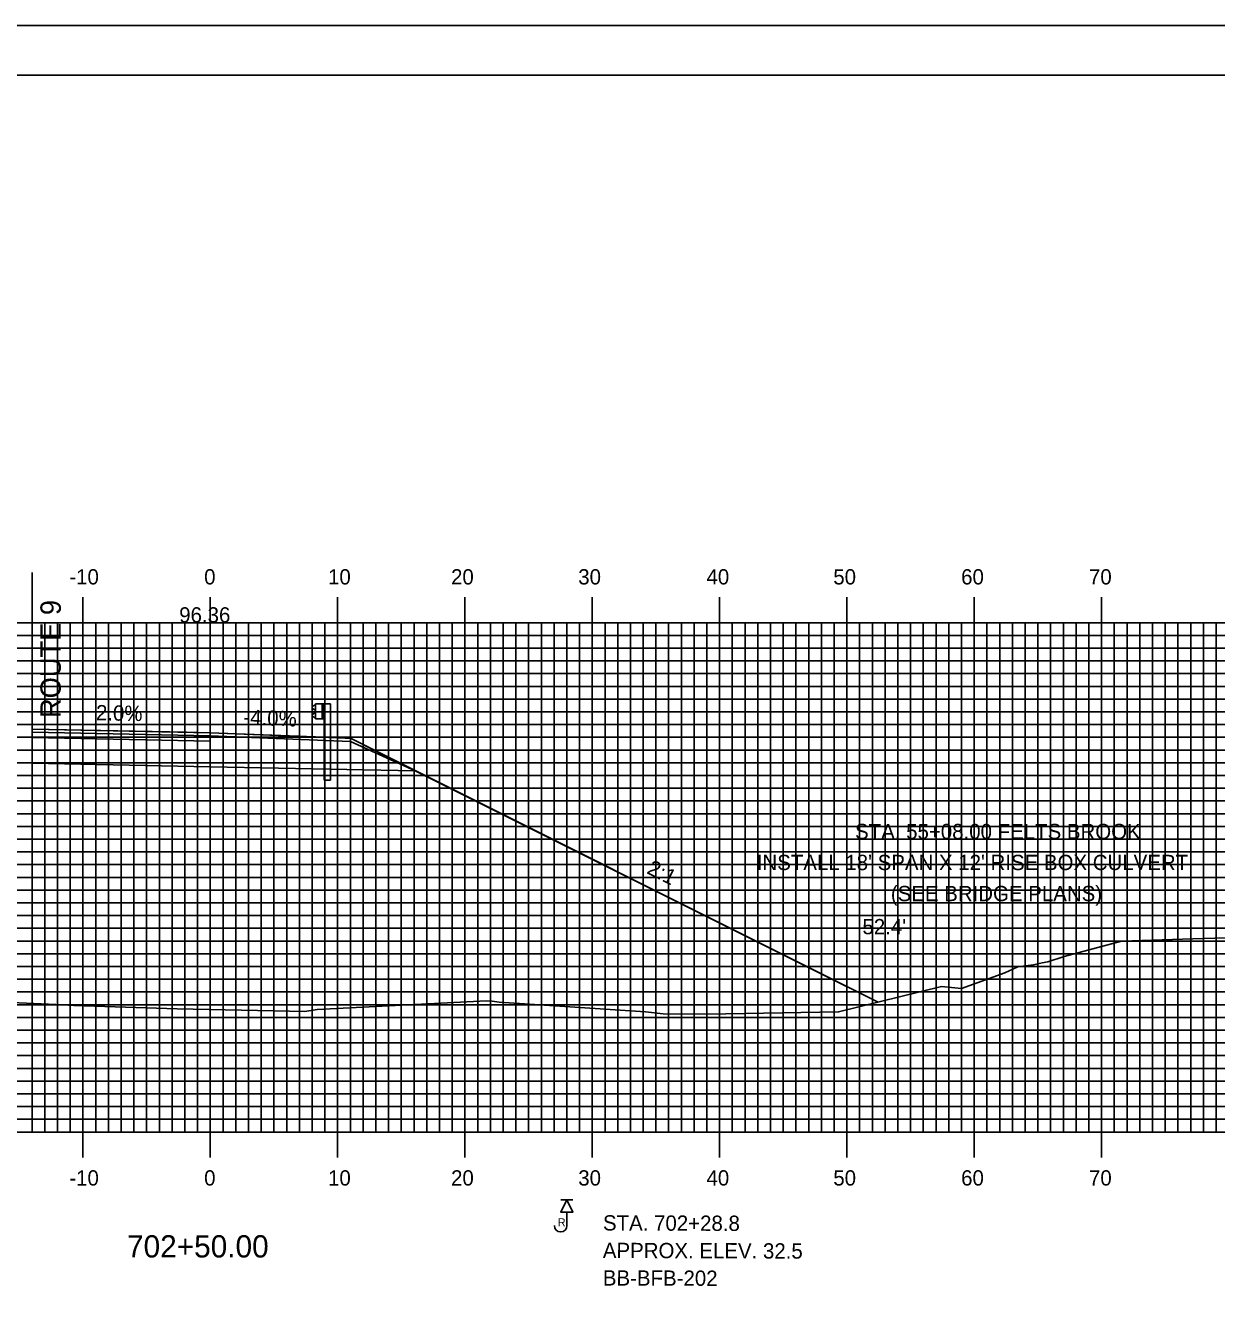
# Model space of a CAD drawing. Extents: x 852936 to 853279, y 364366 to 364586.
# Drawn here: x 853087.2 to 853180.7, y 364484.9 to 364585.7 of the extents above; entities that cross this region are included whole.
import ezdxf

# ---------------------------------------------------------------- set-up
doc = ezdxf.new("R2010")
doc.units = 0
for name, color, linetype in [('ANNOTATION', 7, 'Continuous'), ('BORDER', 7, 'Continuous'), ('BORING - REFUSAL', 7, 'Continuous'), ('D_Guardrail_Beam_Rt', 7, 'Continuous'), ('D_Roadway_Centerline', 7, 'Continuous'), ('D_Roadway_Centerline_Text', 7, 'Continuous'), ('D_Roadway_Edge_Shoulder', 7, 'Continuous'), ('D_Roadway_Edge_TW', 7, 'Continuous'), ('D_Roadway_Pavement', 7, 'Continuous'), ('D_Roadway_SlopeLines', 7, 'Continuous'), ('D_Roadway_SubGrade', 7, 'Continuous'), ('D_Text_Standard', 7, 'Continuous'), ('H_V ANNOTATION', 7, 'Continuous'), ('MAJOR', 7, 'Continuous'), ('MINOR', 7, 'Continuous'), ('PLOT BOUNDARY', 7, 'Continuous'), ('S_Roadway_Centerline', 7, 'Continuous')]:
    doc.layers.add(name, color=color, linetype=linetype)

msp = doc.modelspace()

# ---------------------------------------------------------------- linework, layer by layer
at = {"layer": 'BORDER'}
msp.add_lwpolyline([(852952.09, 364371.79), (853272.09, 364371.79), (853272.09, 364581.79), (852952.09, 364581.79)], close=True, dxfattribs=at)
at = {"layer": 'BORING - REFUSAL'}
for p, q in [((853130.17, 364493.46), (853129.21, 364493.46)), ((853129.69, 364492.5), (853129.69, 364491.44))]:
    msp.add_line(p, q, dxfattribs=at)
msp.add_lwpolyline([(853129.69, 364493.46), (853130.17, 364492.5), (853129.21, 364492.5)], close=True, dxfattribs=at)
msp.add_arc((853129.21, 364491.44), 0.485, 180, 0, dxfattribs=at)
at = {"layer": 'D_Guardrail_Beam_Rt'}
for p, q in [((853109.87, 364532.3), (853109.73, 364532.2)), ((853109.73, 364532.06), (853109.92, 364531.93)), ((853109.96, 364532.33), (853109.89, 364532.31)), ((853109.96, 364532.41), (853110.65, 364532.41)), ((853109.96, 364531.24), (853109.96, 364532.41)), ((853109.96, 364531.86), (853109.96, 364531.79)), ((853110.48, 364532.41), (853110.48, 364531.24)), ((853110.59, 364532.41), (853110.59, 364531.24)), ((853110.65, 364532.41), (853111.12, 364532.41)), ((853110.65, 364532.41), (853110.65, 364531.24)), ((853111.12, 364532.41), (853111.12, 364526.41)), ((853109.92, 364531.73), (853109.73, 364531.59)), ((853109.73, 364531.45), (853109.87, 364531.35)), ((853109.89, 364531.34), (853109.96, 364531.33)), ((853110.65, 364531.24), (853109.96, 364531.24)), ((853110.63, 364526.41), (853110.63, 364531.24)), ((853110.63, 364526.41), (853111.12, 364526.41))]:
    msp.add_line(p, q, dxfattribs=at)
for centre, major_axis, start_param, end_param in [((853109.78, 364532.13), (-0.0877, 0), 5.323254, 7.243116), ((853109.9, 364532.27), (-0.0417, 0), 4.907132, 5.323254), ((853109.88, 364531.86), (0.0789, 0), 0, 0.959931), ((853109.78, 364531.52), (-0.0877, 0), 5.323254, 7.243116), ((853109.9, 364531.38), (-0.0417, 0), 0.959931, 1.376053), ((853109.88, 364531.79), (0.0789, 0), 5.323254, 6.283185)]:
    msp.add_ellipse(centre, major_axis=major_axis, ratio=0.995501, start_param=start_param, end_param=end_param, dxfattribs=at)
at = {"layer": 'D_Roadway_Centerline'}
msp.add_lwpolyline([(853087.69, 364530.43), (853099.81, 364530.18), (853101.69, 364530.15), (853108.62, 364529.87), (853109.69, 364529.83), (853112.29, 364529.72), (853112.69, 364529.71), (853117.1, 364527.5), (853117.79, 364527.16), (853149.2, 364511.45), (853154.14, 364508.98)], dxfattribs=at)
at = {"layer": 'D_Roadway_Edge_Shoulder'}
for points in [[(853101.69, 364530.15), (853112.69, 364529.71), (853112.69, 364529.46), (853101.69, 364529.9)], [(853101.69, 364530.15), (853109.69, 364529.83), (853109.69, 364529.83), (853112.69, 364529.71), (853112.69, 364529.46), (853101.69, 364529.9)], [(853101.69, 364530.15), (853109.69, 364529.83), (853109.69, 364529.83), (853112.69, 364529.71), (853112.69, 364529.46), (853101.69, 364529.9)], [(853101.69, 364530.15), (853112.69, 364529.71), (853112.69, 364529.46), (853101.69, 364529.9)], [(853101.69, 364530.15), (853112.69, 364529.71), (853112.69, 364529.46), (853101.69, 364529.9)]]:
    msp.add_lwpolyline(points, close=True, dxfattribs=at)
at = {"layer": 'D_Roadway_Edge_TW'}
msp.add_lwpolyline([(853087.69, 364530.43), (853101.69, 364530.15), (853101.69, 364529.9), (853087.69, 364530.18)], close=True, dxfattribs=at)
msp.add_lwpolyline([(853087.69, 364530.43), (853101.69, 364530.15), (853101.69, 364529.9), (853087.69, 364530.18)], close=True, dxfattribs=at)
msp.add_lwpolyline([(853087.69, 364530.43), (853101.69, 364530.15), (853101.69, 364529.9), (853087.69, 364530.18)], close=True, dxfattribs=at)
msp.add_lwpolyline([(853087.69, 364530.43), (853101.69, 364530.15), (853101.69, 364529.9), (853087.69, 364530.18)], close=True, dxfattribs=at)
at = {"layer": 'D_Roadway_Pavement'}
msp.add_lwpolyline([(853087.69, 364530.18), (853101.69, 364529.9), (853101.69, 364529.48), (853087.69, 364529.76)], close=True, dxfattribs=at)
msp.add_lwpolyline([(853087.69, 364530.18), (853101.69, 364529.9), (853101.69, 364529.48), (853087.69, 364529.76)], close=True, dxfattribs=at)
msp.add_lwpolyline([(853087.69, 364530.18), (853101.69, 364529.9), (853101.69, 364529.48), (853087.69, 364529.76)], close=True, dxfattribs=at)
msp.add_lwpolyline([(853087.69, 364530.18), (853101.69, 364529.9), (853101.69, 364529.48), (853087.69, 364529.76)], close=True, dxfattribs=at)
msp.add_lwpolyline([(853101.69, 364529.9), (853101.69, 364529.48)], dxfattribs=at)
msp.add_lwpolyline([(853101.69, 364529.9), (853101.69, 364529.48)], dxfattribs=at)
msp.add_lwpolyline([(853101.69, 364529.9), (853101.69, 364529.48)], dxfattribs=at)
msp.add_lwpolyline([(853101.69, 364529.9), (853101.69, 364529.48)], dxfattribs=at)
msp.add_lwpolyline([(853101.69, 364529.9), (853101.69, 364529.48)], dxfattribs=at)
msp.add_lwpolyline([(853101.69, 364529.9), (853101.69, 364529.48)], dxfattribs=at)
msp.add_lwpolyline([(853101.69, 364529.9), (853101.69, 364529.48)], dxfattribs=at)
msp.add_lwpolyline([(853101.69, 364529.9), (853101.69, 364529.48)], dxfattribs=at)
msp.add_lwpolyline([(853101.69, 364529.9), (853101.69, 364529.48)], dxfattribs=at)
msp.add_lwpolyline([(853101.69, 364529.9), (853101.69, 364529.48)], dxfattribs=at)
msp.add_lwpolyline([(853101.69, 364529.9), (853101.69, 364529.48)], dxfattribs=at)
msp.add_lwpolyline([(853101.69, 364529.9), (853101.69, 364529.48)], dxfattribs=at)
msp.add_lwpolyline([(853101.69, 364529.9), (853101.69, 364529.48)], dxfattribs=at)
msp.add_lwpolyline([(853101.69, 364529.9), (853101.69, 364529.48)], dxfattribs=at)
at = {"layer": 'D_Roadway_SlopeLines'}
msp.add_lwpolyline([(853112.69, 364529.71), (853154.14, 364508.98)], dxfattribs=at)
msp.add_lwpolyline([(853112.69, 364529.71), (853154.14, 364508.98)], dxfattribs=at)
msp.add_lwpolyline([(853112.69, 364529.71), (853154.14, 364508.98)], dxfattribs=at)
msp.add_lwpolyline([(853112.69, 364529.71), (853154.14, 364508.98)], dxfattribs=at)
at = {"layer": 'D_Roadway_SubGrade'}
msp.add_line((853087.69, 364542.72), (853087.69, 364527.76), dxfattribs=at)
for points in [[(853101.69, 364529.48), (853101.69, 364529.9), (853112.69, 364529.46), (853112.69, 364529.71), (853117.79, 364527.16), (853101.69, 364527.48)], [(853101.69, 364529.48), (853101.69, 364529.9), (853112.69, 364529.46), (853112.69, 364529.71), (853117.79, 364527.16), (853101.69, 364527.48)], [(853101.69, 364529.48), (853101.69, 364529.9), (853112.69, 364529.46), (853112.69, 364529.71), (853117.79, 364527.16), (853101.69, 364527.48)], [(853101.69, 364529.48), (853101.69, 364529.9), (853112.69, 364529.46), (853117.79, 364527.16), (853101.69, 364527.48)], [(853101.69, 364529.48), (853101.69, 364529.9), (853112.69, 364529.46), (853112.69, 364529.71), (853117.79, 364527.16), (853101.69, 364527.48)], [(853087.69, 364529.76), (853101.69, 364529.48), (853101.69, 364527.48), (853087.69, 364527.76)], [(853087.69, 364529.76), (853101.69, 364529.48), (853101.69, 364527.48), (853087.69, 364527.76)], [(853087.69, 364529.76), (853101.69, 364529.48), (853101.69, 364527.48), (853087.69, 364527.76)], [(853087.69, 364529.76), (853101.69, 364529.48), (853101.69, 364527.48), (853087.69, 364527.76)]]:
    msp.add_lwpolyline(points, close=True, dxfattribs=at)
at = {"layer": 'MAJOR'}
for p, q in [((853091.69, 364540.79), (853091.69, 364538.79)), ((853101.69, 364540.79), (853101.69, 364538.79)), ((853111.69, 364540.79), (853111.69, 364538.79)), ((853121.69, 364540.79), (853121.69, 364538.79)), ((853131.69, 364540.79), (853131.69, 364538.79)), ((853141.69, 364540.79), (853141.69, 364538.79)), ((853151.69, 364540.79), (853151.69, 364538.79)), ((853161.69, 364540.79), (853161.69, 364538.79)), ((853171.69, 364540.79), (853171.69, 364538.79)), ((852961.69, 364538.79), (853241.69, 364538.79)), ((852961.69, 364538.79), (853241.69, 364538.79)), ((853091.69, 364498.79), (853091.69, 364538.79)), ((853101.69, 364498.79), (853101.69, 364538.79)), ((853111.69, 364498.79), (853111.69, 364538.79)), ((853121.69, 364498.79), (853121.69, 364538.79)), ((853131.69, 364498.79), (853131.69, 364538.79)), ((853141.69, 364498.79), (853141.69, 364538.79)), ((853151.69, 364498.79), (853151.69, 364538.79)), ((853161.69, 364498.79), (853161.69, 364538.79)), ((853171.69, 364498.79), (853171.69, 364538.79)), ((852961.69, 364533.79), (853241.69, 364533.79)), ((852961.69, 364528.79), (853241.69, 364528.79)), ((852961.69, 364523.79), (853241.69, 364523.79)), ((852961.69, 364518.79), (853241.69, 364518.79)), ((852961.69, 364513.79), (853241.69, 364513.79)), ((852961.69, 364508.79), (853241.69, 364508.79)), ((852961.69, 364503.79), (853241.69, 364503.79)), ((852961.69, 364498.79), (853241.69, 364498.79)), ((852961.69, 364498.79), (853241.69, 364498.79)), ((853091.69, 364496.78), (853091.69, 364498.79)), ((853101.69, 364496.78), (853101.69, 364498.79)), ((853111.69, 364496.78), (853111.69, 364498.79)), ((853121.69, 364496.78), (853121.69, 364498.79)), ((853131.69, 364496.78), (853131.69, 364498.79)), ((853141.69, 364496.78), (853141.69, 364498.79)), ((853151.69, 364496.78), (853151.69, 364498.79)), ((853161.69, 364496.78), (853161.69, 364498.79)), ((853171.69, 364496.78), (853171.69, 364498.79))]:
    msp.add_line(p, q, dxfattribs=at)
at = {"layer": 'MINOR'}
for p, q in [((853087.69, 364498.79), (853087.69, 364538.79)), ((853088.69, 364498.79), (853088.69, 364538.79)), ((853089.69, 364498.79), (853089.69, 364538.79)), ((853090.69, 364498.79), (853090.69, 364538.79)), ((853092.69, 364498.79), (853092.69, 364538.79)), ((853093.69, 364498.79), (853093.69, 364538.79)), ((853094.69, 364498.79), (853094.69, 364538.79)), ((853095.69, 364498.79), (853095.69, 364538.79)), ((853096.69, 364498.79), (853096.69, 364538.79)), ((853097.69, 364498.79), (853097.69, 364538.79)), ((853098.69, 364498.79), (853098.69, 364538.79)), ((853099.69, 364498.79), (853099.69, 364538.79)), ((853100.69, 364498.79), (853100.69, 364538.79)), ((853102.69, 364498.79), (853102.69, 364538.79)), ((853103.69, 364498.79), (853103.69, 364538.79)), ((853104.69, 364498.79), (853104.69, 364538.79)), ((853105.69, 364498.79), (853105.69, 364538.79)), ((853106.69, 364498.79), (853106.69, 364538.79)), ((853107.69, 364498.79), (853107.69, 364538.79)), ((853108.69, 364498.79), (853108.69, 364538.79)), ((853109.69, 364498.79), (853109.69, 364538.79)), ((853110.69, 364498.79), (853110.69, 364538.79)), ((853112.69, 364498.79), (853112.69, 364538.79)), ((853113.69, 364498.79), (853113.69, 364538.79)), ((853114.69, 364498.79), (853114.69, 364538.79)), ((853115.69, 364498.79), (853115.69, 364538.79)), ((853116.69, 364498.79), (853116.69, 364538.79)), ((853117.69, 364498.79), (853117.69, 364538.79)), ((853118.69, 364498.79), (853118.69, 364538.79)), ((853119.69, 364498.79), (853119.69, 364538.79)), ((853120.69, 364498.79), (853120.69, 364538.79)), ((853122.69, 364498.79), (853122.69, 364538.79)), ((853123.69, 364498.79), (853123.69, 364538.79)), ((853124.69, 364498.79), (853124.69, 364538.79)), ((853125.69, 364498.79), (853125.69, 364538.79)), ((853126.69, 364498.79), (853126.69, 364538.79)), ((853127.69, 364498.79), (853127.69, 364538.79)), ((853128.69, 364498.79), (853128.69, 364538.79)), ((853129.69, 364498.79), (853129.69, 364538.79)), ((853130.69, 364498.79), (853130.69, 364538.79)), ((853132.69, 364498.79), (853132.69, 364538.79)), ((853133.69, 364498.79), (853133.69, 364538.79)), ((853134.69, 364498.79), (853134.69, 364538.79)), ((853135.69, 364498.79), (853135.69, 364538.79)), ((853136.69, 364498.79), (853136.69, 364538.79)), ((853137.69, 364498.79), (853137.69, 364538.79)), ((853138.69, 364498.79), (853138.69, 364538.79)), ((853139.69, 364498.79), (853139.69, 364538.79)), ((853140.69, 364498.79), (853140.69, 364538.79)), ((853142.69, 364498.79), (853142.69, 364538.79)), ((853143.69, 364498.79), (853143.69, 364538.79)), ((853144.69, 364498.79), (853144.69, 364538.79)), ((853145.69, 364498.79), (853145.69, 364538.79)), ((853146.69, 364498.79), (853146.69, 364538.79)), ((853147.69, 364498.79), (853147.69, 364538.79)), ((853148.69, 364498.79), (853148.69, 364538.79)), ((853149.69, 364498.79), (853149.69, 364538.79)), ((853150.69, 364498.79), (853150.69, 364538.79)), ((853152.69, 364498.79), (853152.69, 364538.79)), ((853153.69, 364498.79), (853153.69, 364538.79)), ((853154.69, 364498.79), (853154.69, 364538.79)), ((853155.69, 364498.79), (853155.69, 364538.79)), ((853156.69, 364498.79), (853156.69, 364538.79)), ((853157.69, 364498.79), (853157.69, 364538.79)), ((853158.69, 364498.79), (853158.69, 364538.79)), ((853159.69, 364498.79), (853159.69, 364538.79)), ((853160.69, 364498.79), (853160.69, 364538.79)), ((853162.69, 364498.79), (853162.69, 364538.79)), ((853163.69, 364498.79), (853163.69, 364538.79)), ((853164.69, 364498.79), (853164.69, 364538.79)), ((853165.69, 364498.79), (853165.69, 364538.79)), ((853166.69, 364498.79), (853166.69, 364538.79)), ((853167.69, 364498.79), (853167.69, 364538.79)), ((853168.69, 364498.79), (853168.69, 364538.79)), ((853169.69, 364498.79), (853169.69, 364538.79)), ((853170.69, 364498.79), (853170.69, 364538.79)), ((853172.69, 364498.79), (853172.69, 364538.79)), ((853173.69, 364498.79), (853173.69, 364538.79)), ((853174.69, 364498.79), (853174.69, 364538.79)), ((853175.69, 364498.79), (853175.69, 364538.79)), ((853176.69, 364498.79), (853176.69, 364538.79)), ((853177.69, 364498.79), (853177.69, 364538.79)), ((853178.69, 364498.79), (853178.69, 364538.79)), ((853179.69, 364498.79), (853179.69, 364538.79)), ((853180.69, 364498.79), (853180.69, 364538.79)), ((852961.69, 364537.79), (853241.69, 364537.79)), ((852961.69, 364536.79), (853241.69, 364536.79)), ((852961.69, 364535.79), (853241.69, 364535.79)), ((852961.69, 364534.79), (853241.69, 364534.79)), ((852961.69, 364532.79), (853241.69, 364532.79)), ((852961.69, 364531.79), (853241.69, 364531.79)), ((852961.69, 364530.79), (853241.69, 364530.79)), ((852961.69, 364529.79), (853241.69, 364529.79)), ((852961.69, 364527.79), (853241.69, 364527.79)), ((852961.69, 364526.79), (853241.69, 364526.79)), ((852961.69, 364525.79), (853241.69, 364525.79)), ((852961.69, 364524.79), (853241.69, 364524.79)), ((852961.69, 364522.79), (853241.69, 364522.79)), ((852961.69, 364521.79), (853241.69, 364521.79)), ((852961.69, 364520.79), (853241.69, 364520.79)), ((852961.69, 364519.79), (853241.69, 364519.79)), ((852961.69, 364517.79), (853241.69, 364517.79)), ((852961.69, 364516.79), (853241.69, 364516.79)), ((852961.69, 364515.79), (853241.69, 364515.79)), ((852961.69, 364514.79), (853241.69, 364514.79)), ((852961.69, 364512.79), (853241.69, 364512.79)), ((852961.69, 364511.79), (853241.69, 364511.79)), ((852961.69, 364510.79), (853241.69, 364510.79)), ((852961.69, 364509.79), (853241.69, 364509.79)), ((852961.69, 364507.79), (853241.69, 364507.79)), ((852961.69, 364506.79), (853241.69, 364506.79)), ((852961.69, 364505.79), (853241.69, 364505.79)), ((852961.69, 364504.79), (853241.69, 364504.79)), ((852961.69, 364502.79), (853241.69, 364502.79)), ((852961.69, 364501.79), (853241.69, 364501.79)), ((852961.69, 364500.79), (853241.69, 364500.79)), ((852961.69, 364499.79), (853241.69, 364499.79))]:
    msp.add_line(p, q, dxfattribs=at)
at = {"layer": 'PLOT BOUNDARY'}
msp.add_lwpolyline([(852935.9, 364365.67), (853275.9, 364365.67), (853275.9, 364585.67), (852935.9, 364585.67)], close=True, dxfattribs=at)
at = {"layer": 'S_Roadway_Centerline'}
msp.add_lwpolyline([(853076.23, 364509.4), (853090.13, 364508.79), (853090.97, 364508.73), (853099.09, 364508.46), (853107.91, 364508.28), (853109.11, 364508.27), (853110.09, 364508.41), (853123.39, 364509.1), (853123.82, 364509.06), (853124.38, 364509), (853135.87, 364508.24), (853137.26, 364508.08), (853140.72, 364508.05), (853151.04, 364508.22), (853159.12, 364510.21), (853160.69, 364510.06), (853164.1, 364511.29), (853165.11, 364511.76), (853166.34, 364511.92), (853167.03, 364512.09), (853167.47, 364512.16), (853168.76, 364512.58), (853173.26, 364513.79), (853178.86, 364513.96), (853201.17, 364514.65)], dxfattribs=at)

# ---------------------------------------------------------------- texts
at = {"layer": 'ANNOTATION'}
for s, height, rotation, p in [('ROUTE 9', 1.6, 90, (853089.95, 364531.3)), ('2.0%', 1.2, 358.8542, (853092.7, 364531.13)), ('-4.0%', 1.2, 357.7094, (853104.27, 364530.79)), ('2:1', 1.2, 333.4349, (853135.9, 364519.14))]:
    msp.add_text(s, height=height, rotation=rotation, dxfattribs=at).set_placement(p)
for s, p in [('STA. 55+08.00 FELTS BROOK', (853152.33, 364521.79)), ("INSTALL 18' SPAN X 12' RISE BOX CULVERT", (853144.61, 364519.36)), ('(SEE BRIDGE PLANS)', (853155.14, 364516.92))]:
    msp.add_text(s, height=1.2, dxfattribs=at).set_placement(p)
at = {"layer": 'BORING - REFUSAL'}
msp.add_text('R', height=0.64, dxfattribs=at).set_placement((853128.98, 364491.38))
for s, p in [('STA. 702+28.8', (853132.53, 364491.06)), ('APPROX. ELEV. 32.5', (853132.52, 364488.9)), ('BB-BFB-202', (853132.52, 364486.74))]:
    msp.add_text(s, height=1.2, rotation=359.8142, dxfattribs=at).set_placement(p)
at = {"layer": 'D_Roadway_Centerline_Text'}
msp.add_text('96.36', height=1.2, dxfattribs=at).set_placement((853099.25, 364538.8))
at = {"layer": 'D_Text_Standard'}
msp.add_text("52.4'", height=1.2, dxfattribs=at).set_placement((853152.91, 364514.32))
at = {"layer": 'H_V ANNOTATION'}
for s, height, p in [('-10', 1.2, (853090.62, 364541.79)), ('0', 1.2, (853101.21, 364541.79)), ('10', 1.2, (853110.94, 364541.79)), ('20', 1.2, (853120.6, 364541.79)), ('30', 1.2, (853130.59, 364541.79)), ('40', 1.2, (853140.66, 364541.79)), ('50', 1.2, (853150.62, 364541.79)), ('60', 1.2, (853160.66, 364541.79)), ('70', 1.2, (853170.7, 364541.79)), ('-10', 1.2, (853090.62, 364494.59)), ('0', 1.2, (853101.21, 364494.59)), ('10', 1.2, (853110.94, 364494.59)), ('20', 1.2, (853120.6, 364494.59)), ('30', 1.2, (853130.59, 364494.59)), ('40', 1.2, (853140.66, 364494.59)), ('50', 1.2, (853150.62, 364494.59)), ('60', 1.2, (853160.66, 364494.59)), ('70', 1.2, (853170.7, 364494.59)), ('702+50.00', 1.75, (853095.15, 364488.94))]:
    msp.add_text(s, height=height, dxfattribs=at).set_placement(p)

doc.saveas('drawing.dxf')
